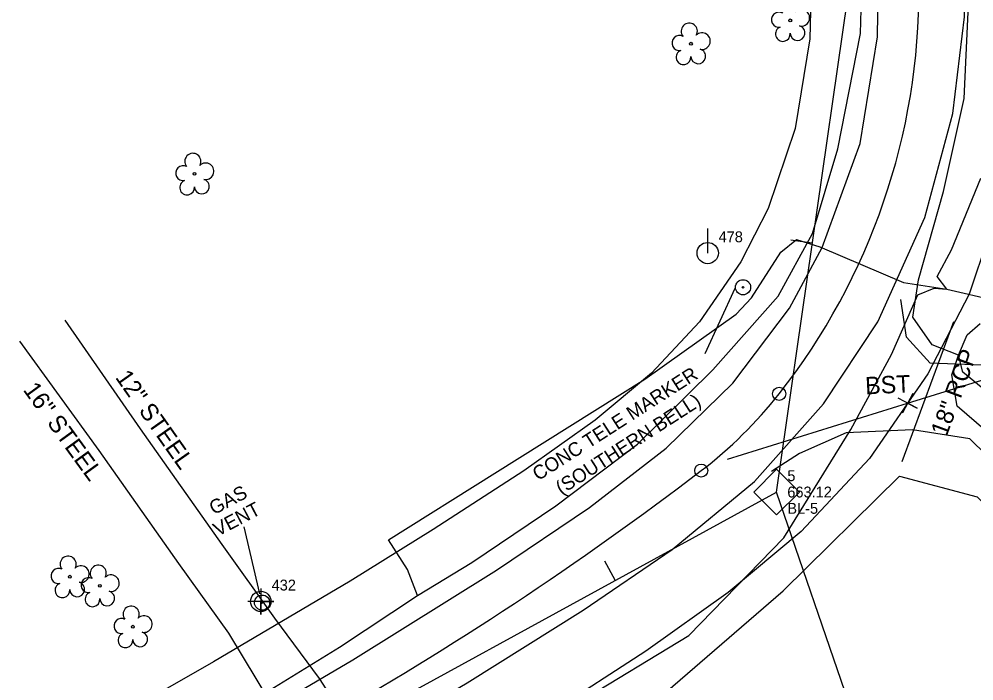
# Model space of a CAD drawing. Extents: x 1380524 to 1382335, y 594765 to 596944.
# Drawn here: x 1381675.7 to 1381895.1, y 595571.8 to 595723.8 of the extents above; entities that cross this region are included whole.
import ezdxf

# ---------------------------------------------------------------- set-up
doc = ezdxf.new("R2010")
doc.units = 0
for name, color, linetype in [('CTL Supplemental Horizontal and Vertical Cogo Comment', 7, 'Continuous'), ('CTL Supplemental Horizontal and Vertical Cogo Elevation', 7, 'Continuous'), ('Exist Horizontal Alignment', 7, 'Continuous'), ('Exist Horizontal Alignment Station Label', 7, 'Continuous'), ('Exist Horizontal Baseline Alignment', 7, 'Continuous'), ('Exist Horizontal Baseline Alignment Station Label', 7, 'Continuous'), ('Exist Horizontal Baseline Alignment Tick small', 7, 'Continuous'), ('Exist Other Culture Fence Line', 7, 'Continuous'), ('Exist Property Tie Line', 7, 'Continuous'), ('Exist Roads EOP', 7, 'Continuous'), ('Exist Roads EOP Other', 7, 'Continuous'), ('Exist Roads Soil', 7, 'Continuous'), ('Exist Structure Major Bridge WW', 7, 'Continuous'), ('Exist Structure Minor Pipes RCP 18 Inch', 7, 'Continuous'), ('Exist Structure Minor Pipes RCP 18 Inch Text', 7, 'Continuous'), ('Exist Utilities Gas UG Line Cogo Number', 7, 'Continuous'), ('Exist Utilities Gas UG Line Cogo Point CELL', 7, 'Continuous'), ('Exist Utilities Gas UG Line SUE', 7, 'Continuous'), ('Exist Utilities Gas UG Line SUE Text', 7, 'Continuous'), ('Exist Utilities Other Located Object Leader', 7, 'Continuous'), ('Exist Utilities Power Tower Text', 7, 'Continuous'), ('Exist Utilities Telephone UG Cable', 7, 'Continuous'), ('Exist Vegetation Tree CELL', 7, 'Continuous'), ('Prop Earthen Structure Cut Ditch Special Detail CELL', 7, 'Continuous'), ('Prop Earthen Structure Cut Ditch Special Detail Label', 7, 'Continuous'), ('Prop Earthen Structure Ditch Flow Line', 7, 'Continuous'), ('Prop Erosion Rip Rap At Embankment Detail CELL', 7, 'Continuous'), ('Prop Horizontal Alignment Tick Large', 7, 'Continuous'), ('Prop Horizontal Alignment Tick Small', 7, 'Continuous'), ('Prop SS Cut Line', 7, 'Continuous')]:
    doc.layers.add(name, color=color, linetype=linetype)

# ---------------------------------------------------------------- blocks, each defined once
blk = doc.blocks.new('EXIST VEGETATION TREE')
at = {"layer": 'Prop Erosion Rip Rap At Embankment Detail CELL'}
blk.add_line((0, 0), (0, 0), dxfattribs=at)
blk.add_circle((0, 0), 0.00652, dxfattribs=at)
for centre, radius, start, end in [((-0.0077, 0.0575), 0.0371, 330.1651, 219.7134), ((0.051, 0.0118), 0.038, 257.1011, 134.1999), ((-0.0521, 0.0031), 0.0345, 62.6636, 279.3457), ((-0.0341, -0.0624), 0.0338, 111.5671, 6.231), ((0.0335, -0.058), 0.034, 181.2822, 74.56)]:
    blk.add_arc(centre, radius, start, end, dxfattribs=at)
blk = doc.blocks.new('EXIST UTILITIES POWER POLE')
at = {"layer": 'Exist Other Culture Fence Line'}
for q in [(0, 0.1125), (0, 0)]:
    blk.add_line((0, 0), q, dxfattribs=at)
blk.add_circle((0, 0), 0.049, dxfattribs=at)
blk = doc.blocks.new('EXIST UTILITIES OTHER LOCATED OBJECT')
at = {"layer": 'Prop Earthen Structure Cut Ditch Special Detail CELL'}
for radius in [0.0436, 0.0048]:
    blk.add_circle((0, 0), radius, dxfattribs=at)

msp = doc.modelspace()

# ---------------------------------------------------------------- linework, layer by layer
at = {"layer": 'Exist Horizontal Alignment'}
for centre, radius, start, end in [((1381732.46, 595730.53), 150, 321.7878, 0.3204), ((1381732.46, 595730.53), 150, 321.7878, 0.3204), ((1381732.46, 595730.53), 150, 321.7878, 0.3204), ((1381771.75, 595699.6), 100, 307.3503, 321.7878), ((1381771.75, 595699.6), 100, 307.3503, 321.7878), ((1381771.75, 595699.6), 100, 307.3503, 321.7878), ((1381362.24, 596236.19), 775, 299.56117, 307.3503), ((1381362.24, 596236.19), 775, 299.56117, 307.3503), ((1381362.24, 596236.19), 775, 299.56117, 307.3503)]:
    msp.add_arc(centre, radius, start, end, dxfattribs=at)
at = {"layer": 'Exist Horizontal Alignment Station Label'}
for centre in [(1381850.32, 595637.74), (1381832.42, 595620.11)]:
    msp.add_circle(centre, 1.5, dxfattribs=at)
at = {"layer": 'Exist Horizontal Baseline Alignment'}
for p, q in [((1381849.7, 595615.16), (1381880.58, 595829.47)), ((1381525.59, 595437.8), (1381849.7, 595615.16))]:
    msp.add_line(p, q, dxfattribs=at)
at = {"layer": 'Exist Horizontal Baseline Alignment Station Label'}
msp.add_line((1381873.53, 595545.87), (1381849.7, 595615.16), dxfattribs=at)
at = {"layer": 'Exist Horizontal Baseline Alignment Tick small'}
for p, q in [((1381857.94, 595672.34), (1381852.99, 595673.05)), ((1381812.65, 595594.89), (1381810.25, 595599.28))]:
    msp.add_line(p, q, dxfattribs=at)
at = {"layer": 'Exist Other Culture Fence Line'}
for q in [(1381833.9, 595675.69), (1381833.9, 595670.06)]:
    msp.add_line((1381833.9, 595670.06), q, dxfattribs=at)
msp.add_circle((1381833.9, 595670.06), 2.45, dxfattribs=at)
at = {"layer": 'Exist Property Tie Line'}
msp.add_line((1381838.47, 595622.74), (1381879.85, 595635.61), dxfattribs=at)
at = {"layer": 'Exist Roads EOP'}
for points in [[(1381895.92, 595822.17), (1381902.47, 595793.76), (1381906.2, 595769.7), (1381907.97, 595742.61), (1381907.23, 595714.6), (1381902.73, 595686.65), (1381893.97, 595660.65), (1381884.45, 595642.32), (1381871.1, 595622.85), (1381855.36, 595606.07), (1381838.64, 595592.06), (1381819.68, 595578.62), (1381797.68, 595564.39), (1381777.69, 595551.91), (1381745.42, 595532.92), (1381704.18, 595509.33)], [(1381847.19, 595810.94), (1381853.34, 595784.3), (1381856.45, 595764.22), (1381857.93, 595741.64), (1381857.34, 595719.26), (1381854.03, 595698.69), (1381847.82, 595680.28), (1381841.48, 595668.07), (1381832.02, 595654.27), (1381820.95, 595642.47), (1381808.08, 595631.69), (1381791.64, 595620.03), (1381770.85, 595606.59), (1381751.76, 595594.66), (1381720.33, 595576.17), (1381679.35, 595552.72)]]:
    msp.add_lwpolyline(points, dxfattribs=at)
at = {"layer": 'Exist Roads EOP Other'}
for points in [[(1382105.64, 595686.55), (1382076.86, 595688.73), (1382055.65, 595687.52), (1382013.67, 595678.93), (1381981.76, 595668.62), (1381934.99, 595653.84), (1381898.93, 595644.26), (1381885.04, 595644.78), (1381879.57, 595650.76), (1381878.26, 595659.39)], [(1381894.12, 595627.41), (1381880.98, 595629.48), (1381865.72, 595628.74), (1381854.99, 595624.06), (1381848.58, 595619.86)], [(1382017.25, 595495.9), (1381988.8, 595527.93), (1381969.42, 595549.67), (1381936.78, 595585.55), (1381894.12, 595627.41)]]:
    msp.add_lwpolyline(points, dxfattribs=at)
at = {"layer": 'Exist Structure Major Bridge WW'}
msp.add_line((1381879.85, 595635.61), (1381879.85, 595635.61), dxfattribs=at)
msp.add_lwpolyline([(1381881.01, 595637.82), (1381878.68, 595633.39), (1381879.85, 595635.61), (1381882.06, 595634.44), (1381877.63, 595636.77)], dxfattribs=at)
at = {"layer": 'Exist Structure Minor Pipes RCP 18 Inch'}
msp.add_lwpolyline([(1381890.37, 595654.26), (1381878.49, 595622.13)], dxfattribs=at)
at = {"layer": 'Exist Utilities Gas UG Line Cogo Point CELL'}
msp.add_lwpolyline([(1381731.2, 595593.05), (1381731.2, 595587.05), (1381731.2, 595590.05), (1381734.2, 595590.05), (1381728.2, 595590.05)], dxfattribs=at)
msp.add_circle((1381731.2, 595590.05), 2.34, dxfattribs=at)
at = {"layer": 'Exist Utilities Gas UG Line SUE'}
for p, q in [((1381686.15, 595654.62), (1381703.49, 595629.73)), ((1381675.73, 595649.81), (1381694.01, 595624.7)), ((1381703.49, 595629.73), (1381722.24, 595603.15)), ((1381694.01, 595624.7), (1381712.29, 595598.76)), ((1381722.24, 595603.15), (1381734.34, 595586.17)), ((1381712.29, 595598.76), (1381723.79, 595582.73)), ((1381734.34, 595586.17), (1381744.6, 595572.32)), ((1381723.79, 595582.73), (1381734.02, 595565.83)), ((1381744.6, 595572.32), (1381754.84, 595556.7))]:
    msp.add_line(p, q, dxfattribs=at)
at = {"layer": 'Exist Utilities Other Located Object Leader'}
for points in [[(1381840.16, 595661.91), (1381833.22, 595646.89)], [(1381730.95, 595591.77), (1381727.36, 595607.16)]]:
    msp.add_lwpolyline(points, dxfattribs=at)
at = {"layer": 'Exist Utilities Power Tower Text'}
msp.add_line((1381879.85, 595635.61), (1382234.24, 595745.79), dxfattribs=at)
at = {"layer": 'Exist Utilities Telephone UG Cable'}
for p, q in [((1381868.99, 595720.53), (1381869.73, 595748.41)), ((1381892.86, 595705.57), (1381894.08, 595733.51)), ((1381863.81, 595694.03), (1381868.99, 595720.53)), ((1381888.07, 595684.18), (1381892.86, 595705.57)), ((1381857.97, 595674.57), (1381863.81, 595694.03)), ((1381889.95, 595670.78), (1381896.64, 595687.3)), ((1381882.32, 595663.89), (1381888.07, 595684.18)), ((1381850.09, 595660.15), (1381857.97, 595674.57)), ((1381850.73, 595670.24), (1381854.33, 595673.17)), ((1381854.33, 595673.17), (1381859.69, 595671.48)), ((1381859.69, 595671.48), (1381878.89, 595663.31)), ((1381886.61, 595664.68), (1381889.95, 595670.78)), ((1381843.97, 595659.77), (1381850.73, 595670.24)), ((1381881.05, 595655.36), (1381882.32, 595663.89)), ((1381888.87, 595661.8), (1381886.61, 595664.68)), ((1381878.89, 595663.31), (1381888.87, 595661.8)), ((1381882.2, 595660.45), (1381885.94, 595662.02)), ((1381885.94, 595662.02), (1381888.87, 595661.8)), ((1381888.87, 595661.8), (1381901.65, 595658.8)), ((1381835.1, 595643.26), (1381850.09, 595660.15)), ((1381840.42, 595656), (1381843.97, 595659.77)), ((1381876.14, 595646.79), (1381882.2, 595660.45)), ((1381819.43, 595641.07), (1381840.42, 595656)), ((1381885.45, 595648.98), (1381881.05, 595655.36)), ((1381893.52, 595651.3), (1381896.49, 595653.89)), ((1381891.53, 595646.58), (1381893.52, 595651.3)), ((1381891.53, 595646.58), (1381885.45, 595648.98)), ((1381866.8, 595629.54), (1381876.14, 595646.79)), ((1381890.01, 595642.07), (1381891.53, 595646.58)), ((1381892.51, 595642.73), (1381891.53, 595646.58)), ((1381817.78, 595626.16), (1381835.1, 595643.26)), ((1381891.2, 595634.87), (1381890.01, 595642.07)), ((1381919.85, 595620.12), (1381892.51, 595642.73)), ((1381784.95, 595619.47), (1381819.43, 595641.07)), ((1381913.61, 595615.68), (1381891.2, 595634.87)), ((1381851.36, 595604.65), (1381866.8, 595629.54)), ((1381799.03, 595612.01), (1381817.78, 595626.16)), ((1381760.56, 595604.21), (1381784.95, 595619.47)), ((1381779.69, 595598.97), (1381799.03, 595612.01)), ((1381829.59, 595582.19), (1381851.36, 595604.65)), ((1381764.93, 595597.41), (1381760.56, 595604.21)), ((1381767.19, 595591.44), (1381779.69, 595598.97)), ((1381767.19, 595591.44), (1381764.93, 595597.41)), ((1381749.29, 595579.5), (1381767.19, 595591.44)), ((1381803.59, 595566.49), (1381829.59, 595582.19)), ((1381729.38, 595567.32), (1381749.29, 595579.5))]:
    msp.add_line(p, q, dxfattribs=at)
at = {"layer": 'Prop Earthen Structure Cut Ditch Special Detail Label'}
msp.add_lwpolyline([(1381970.28, 595535.93), (1381960.54, 595518.19), (1381827.03, 595492.89), (1381805.59, 595553.01), (1381851.27, 595592.48), (1381878.01, 595618.84), (1381895.83, 595614.04), (1381941.37, 595569.31), (1381971.15, 595535.75)], dxfattribs=at)
at = {"layer": 'Prop Earthen Structure Ditch Flow Line'}
for points in [[(1381695.4, 595522.74), (1381736.81, 595546.71), (1381778.65, 595571.33), (1381805.29, 595588.06), (1381825.76, 595602.01), (1381844.65, 595617.61), (1381860.52, 595635.43), (1381873.02, 595654.26), (1381883.82, 595678.23), (1381890.26, 595702.1), (1381892.88, 595724.32), (1381892.54, 595747.98), (1381889.9, 595776.18), (1381882.89, 595811.47), (1381872.74, 595847.05), (1381870.77, 595854.96), (1381871.9, 595862.06), (1381875.4, 595867.69)], [(1381686.7, 595538.62), (1381723.5, 595559.64), (1381752.33, 595576.66), (1381785.4, 595597.24), (1381806.72, 595611.59), (1381824.38, 595625.23), (1381839.64, 595640.2), (1381852.72, 595657.45), (1381860.22, 595671.32), (1381868.91, 595695.27), (1381872.89, 595719.75), (1381873.33, 595746.52), (1381871.37, 595770.38), (1381866.55, 595797.62), (1381860.1, 595823.76)]]:
    msp.add_lwpolyline(points, dxfattribs=at)
at = {"layer": 'Prop SS Cut Line'}
msp.add_line((1381849.7, 595615.16), (1381849.7, 595615.16), dxfattribs=at)
msp.add_lwpolyline([(1381844.48, 595615.18), (1381849.72, 595620.42), (1381854.97, 595615.17), (1381849.73, 595609.93)], close=True, dxfattribs=at)

# ---------------------------------------------------------------- block references
at = {"layer": 'Exist Other Culture Fence Line', "xscale": 50, "yscale": 50}
msp.add_blockref('EXIST UTILITIES POWER POLE', (1381833.9, 595670.06), dxfattribs=at)
at = {"layer": 'Prop Earthen Structure Cut Ditch Special Detail CELL', "xscale": 40, "yscale": 40}
for p in [(1381842.02, 595662.21), (1381731.5, 595589.77)]:
    msp.add_blockref('EXIST UTILITIES OTHER LOCATED OBJECT', p, dxfattribs=at)
at = {"layer": 'Prop Erosion Rip Rap At Embankment Detail CELL', "xscale": 50, "yscale": 50}
for p in [(1381852.88, 595723.52), (1381830.05, 595718.17), (1381715.98, 595688.26), (1381687.33, 595595.73), (1381694.24, 595593.64), (1381701.81, 595584.24)]:
    msp.add_blockref('EXIST VEGETATION TREE', p, dxfattribs=at)

# ---------------------------------------------------------------- texts
at = {"layer": 'CTL Supplemental Horizontal and Vertical Cogo Comment'}
msp.add_text('BL-5', height=2.5, dxfattribs=at).set_placement((1381852.2, 595610.17))
at = {"layer": 'CTL Supplemental Horizontal and Vertical Cogo Elevation'}
msp.add_text('663.12', height=2.5, dxfattribs=at).set_placement((1381852.2, 595613.92))
at = {"layer": 'Exist Roads Soil'}
msp.add_text('5', height=2.5, dxfattribs=at).set_placement((1381852.2, 595617.67))
at = {"layer": 'Exist Structure Minor Pipes RCP 18 Inch Text'}
msp.add_text('18" RCP', height=4, rotation=69.7125, dxfattribs=at).set_placement((1381888.77, 595627.7))
at = {"layer": 'Exist Utilities Gas UG Line Cogo Number'}
msp.add_text('432', height=2.5, dxfattribs=at).set_placement((1381733.7, 595592.55))
at = {"layer": 'Exist Utilities Gas UG Line SUE Text'}
for s, rotation, p in [('12" STEEL', 305.2043, (1381697.64, 595641.49)), ('16" STEEL', 306.044, (1381676.45, 595638.63))]:
    msp.add_text(s, height=4, rotation=rotation, dxfattribs=at).set_placement(p)
at = {"layer": 'Exist Vegetation Tree CELL'}
msp.add_text('478', height=2.5, dxfattribs=at).set_placement((1381836.4, 595672.56))
msp.add_text('478', height=2.5, dxfattribs=at).set_placement((1381836.4, 595672.56))
at = {"layer": 'Prop Horizontal Alignment Tick Large'}
msp.add_text('BST', height=4, rotation=2.7705, dxfattribs=at).set_placement((1381870.18, 595637.59))
at = {"layer": 'Prop Horizontal Alignment Tick Small'}
for s, rotation, p in [('CONC TELE MARKER', 32.7142, (1381794.94, 595617.65)), ('(SOUTHERN BELL)', 32.7142, (1381800.28, 595614.44)), ('GAS', 27.7977, (1381720.43, 595609.84)), ('VENT', 27.7977, (1381721.35, 595604.9))]:
    msp.add_text(s, height=3.2, rotation=rotation, dxfattribs=at).set_placement(p)

doc.saveas('drawing.dxf')
